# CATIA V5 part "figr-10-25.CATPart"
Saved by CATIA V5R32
Part number: Part1
Bounding box of the stored display mesh (mm): x -92.502 to 25.581, y -200.404 to 0, z 0 to 47.305
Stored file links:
  D:\PROJECTS\Project 2022\CATIA V5 6R 2022\Resources\Part Files\c10_catia_v5_6r2022_prt\c10_catia_v5_6r2022_prt\figr-10-25.CATPart
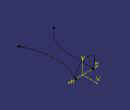
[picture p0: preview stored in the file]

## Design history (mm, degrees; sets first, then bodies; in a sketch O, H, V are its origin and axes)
Set1
  Sketch1 on xy-plane, origin (0, 0, 0), H (1, 0, 0), V (0, 1, 0)
    spline S1 through (-36.6295, 0) (-39.5961, -76.7629) (-56.6868, -154.7631) (-92.5015, -194.2587)
    point P1 (-36.6295, 0)
    coincidence: P1 H
  Sketch2 on xy-plane, origin (0, 0, 0), H (1, 0, 0), V (0, 1, 0)
    spline S1 through (25.5807, 0) (5.5021, -50.6307) (25.5807, -200.404)
    point P1 (25.5807, 0)
    coincidence: P1 H
  Sketch3 on zx-plane, origin (0, 0, 0), H (-1, 0, 0), V (0, 0, 1)
    spline S1 through (-25.5807, 0) (16.4189, 47.2175) (28.9802, 46.33) (36.6295, 0)
    reference projected point E1 (36.6295, 0) from vertex of Sketch1
    reference projected point E2 (-25.5807, 0) from vertex of Sketch2
    point P1 (-25.5807, 0)
    point P2 (36.6295, 0)
    coincidence: P1 H, P2 H, E1 P2, P1 E2
Body1 (main body)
